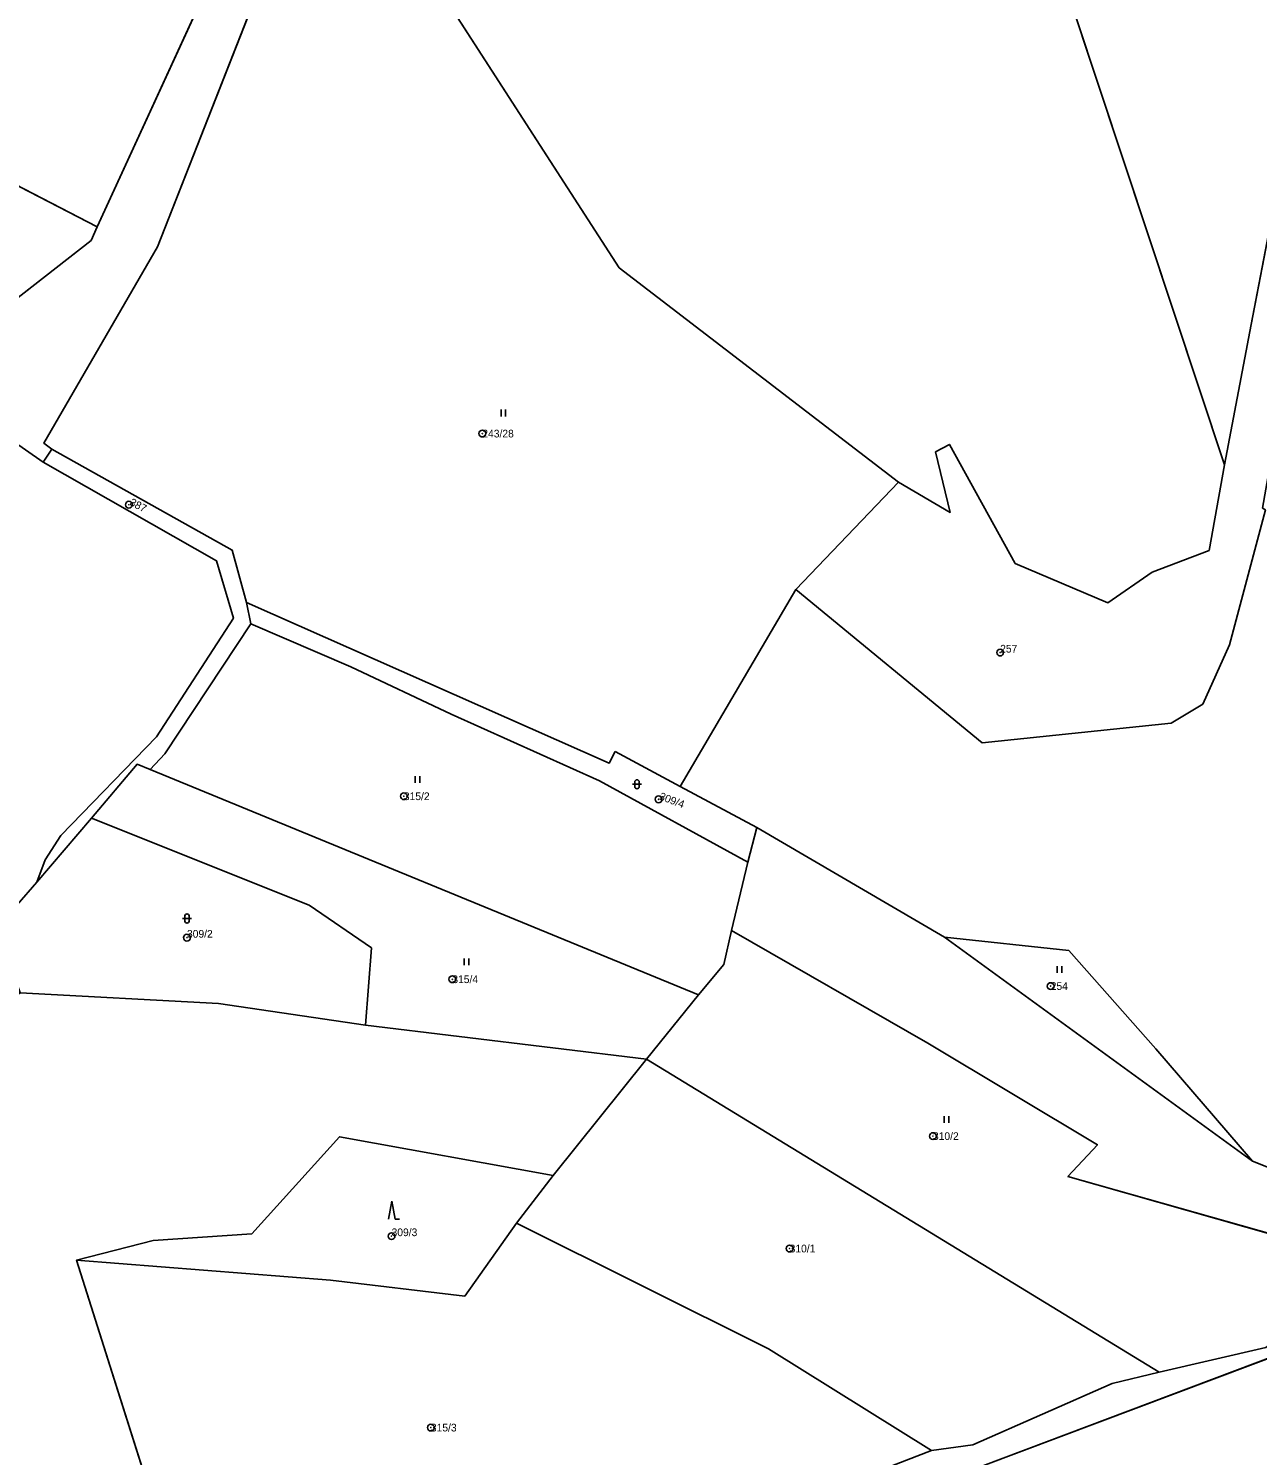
# Model space of a CAD drawing. Extents: x -652854 to -650068, y -1097661 to -1095417.
# Drawn here: x -651121.4 to -650849.8, y -1097086.2 to -1096771 of the extents above; entities that cross this region are included whole.
import ezdxf

# ---------------------------------------------------------------- set-up
doc = ezdxf.new("R2010")
doc.units = 0
for name, color, linetype in [('Definiční body parcel', 7, 'Continuous'), ('Hranice parcel', 7, 'Continuous'), ('Obvody jako plochy', 7, 'Continuous'), ('Parcelní čísla', 7, 'Continuous'), ('Značky kultur', 7, 'Continuous')]:
    doc.layers.add(name, color=color, linetype=linetype)

msp = doc.modelspace()

# ---------------------------------------------------------------- linework, layer by layer
at = {"layer": 'Definiční body parcel'}
for centre, radius in [((-651021.11, -1096860.46), 0.75), ((-651021.11, -1096860.46), 0.0327), ((-651099.22, -1096876.17), 0.75), ((-651099.22, -1096876.17), 0.0327), ((-650906.68, -1096908.84), 0.75), ((-650906.68, -1096908.84), 0.0327), ((-651038.45, -1096940.59), 0.75), ((-651038.45, -1096940.59), 0.0327), ((-650982.16, -1096941.26), 0.75), ((-650982.16, -1096941.26), 0.0327), ((-651086.38, -1096971.83), 0.75), ((-651086.38, -1096971.83), 0.0327), ((-651027.74, -1096981.02), 0.75), ((-651027.74, -1096981.02), 0.0327), ((-650895.51, -1096982.53), 0.75), ((-650895.51, -1096982.53), 0.0327), ((-650921.53, -1097015.68), 0.75), ((-650921.53, -1097015.68), 0.0327), ((-651041.17, -1097037.78), 0.75), ((-651041.17, -1097037.78), 0.0327), ((-650953.2, -1097040.52), 0.75), ((-650953.2, -1097040.52), 0.0327), ((-651032.48, -1097080.08), 0.75), ((-651032.48, -1097080.08), 0.0327)]:
    msp.add_circle(centre, radius, dxfattribs=at)
at = {"layer": 'Hranice parcel'}
for p, q in [((-651054.18, -1096725.78), (-650990.9, -1096823.82)), ((-651106.25, -1096814.79), (-651073.19, -1096742.86)), ((-651064.16, -1096746.02), (-651092.91, -1096819.19)), ((-651234.33, -1096748.53), (-651106.25, -1096814.79)), ((-650857.12, -1096867.39), (-650895.72, -1096750.97)), ((-650839.76, -1096776.84), (-650851.23, -1096836.35)), ((-651107.57, -1096817.82), (-651106.25, -1096814.79)), ((-651148.03, -1096849.31), (-651107.57, -1096817.82)), ((-651092.91, -1096819.19), (-651118.03, -1096862.54)), ((-650990.9, -1096823.82), (-650929.11, -1096871.18)), ((-650851.23, -1096836.35), (-650857.12, -1096867.39)), ((-651118.15, -1096866.81), (-651139.25, -1096852.14)), ((-651118.03, -1096862.54), (-651116.22, -1096863.89)), ((-650917.88, -1096862.87), (-650920.95, -1096864.52)), ((-650903.36, -1096889.13), (-650917.88, -1096862.87)), ((-651118.15, -1096866.81), (-651116.22, -1096863.89)), ((-651116.22, -1096863.89), (-651076.39, -1096886.18)), ((-650920.95, -1096864.52), (-650917.75, -1096877.86)), ((-651079.85, -1096888.57), (-651118.15, -1096866.81)), ((-650857.12, -1096867.39), (-650860.53, -1096886.28)), ((-650929.11, -1096871.18), (-650951.86, -1096894.94)), ((-650917.75, -1096877.86), (-650929.11, -1096871.18)), ((-650855.98, -1096907.12), (-650848.06, -1096877.3)), ((-651076.39, -1096886.18), (-651073.22, -1096897.77)), ((-650860.53, -1096886.28), (-650873.06, -1096891.08)), ((-651076.13, -1096901.24), (-651079.85, -1096888.57)), ((-650882.88, -1096897.84), (-650903.36, -1096889.13)), ((-650873.06, -1096891.08), (-650882.88, -1096897.84)), ((-650993.08, -1096933.27), (-651073.22, -1096897.77)), ((-651073.22, -1096897.77), (-651072.28, -1096902.46)), ((-650951.86, -1096894.94), (-650977.36, -1096938.43)), ((-650951.86, -1096894.94), (-650910.63, -1096928.8)), ((-651093.14, -1096927.43), (-651076.13, -1096901.24)), ((-651072.28, -1096902.46), (-651091.25, -1096931.23)), ((-651072.28, -1096902.46), (-651050.19, -1096912)), ((-650861.91, -1096920.25), (-650855.98, -1096907.12)), ((-651050.19, -1096912), (-651027.98, -1096922.47)), ((-651027.98, -1096922.47), (-650995.25, -1096937.21)), ((-650868.88, -1096924.45), (-650861.91, -1096920.25)), ((-650910.63, -1096928.8), (-650868.88, -1096924.45)), ((-651114.25, -1096949.24), (-651093.14, -1096927.43)), ((-651091.25, -1096931.23), (-651094.49, -1096934.71)), ((-650991.73, -1096930.73), (-650993.08, -1096933.27)), ((-650977.36, -1096938.43), (-650991.73, -1096930.73)), ((-651097.4, -1096933.5), (-651107.5, -1096945.41)), ((-651094.49, -1096934.71), (-651097.4, -1096933.5)), ((-650973.32, -1096984.48), (-651094.49, -1096934.71)), ((-650995.25, -1096937.21), (-650962.41, -1096955.12)), ((-650960.43, -1096947.51), (-650977.36, -1096938.43)), ((-651107.5, -1096945.41), (-651119.55, -1096959.6)), ((-651059.41, -1096964.67), (-651107.5, -1096945.41)), ((-650962.41, -1096955.12), (-650960.43, -1096947.51)), ((-650918.97, -1096971.74), (-650960.43, -1096947.51)), ((-651117.7, -1096954.62), (-651114.25, -1096949.24)), ((-651119.55, -1096959.6), (-651117.7, -1096954.62)), ((-650962.41, -1096955.12), (-650966.07, -1096970.24)), ((-651119.55, -1096959.6), (-651128.3, -1096969.57)), ((-651045.61, -1096974.1), (-651059.41, -1096964.67)), ((-650967.75, -1096977.76), (-650966.07, -1096970.24)), ((-650966.07, -1096970.24), (-650922.68, -1096995.13)), ((-650850.91, -1097021.2), (-650918.97, -1096971.74)), ((-650918.97, -1096971.74), (-650891.5, -1096974.68)), ((-651046.91, -1096991.17), (-651045.61, -1096974.1)), ((-650891.5, -1096974.68), (-650872.31, -1096996.42)), ((-650973.32, -1096984.48), (-650967.75, -1096977.76)), ((-651123.24, -1096984.03), (-651079.38, -1096986.4)), ((-650984.81, -1096998.67), (-650973.32, -1096984.48)), ((-651079.38, -1096986.4), (-651046.91, -1096991.17)), ((-650984.81, -1096998.67), (-651046.91, -1096991.17)), ((-650922.68, -1096995.13), (-650885.18, -1097017.6)), ((-651005.44, -1097024.35), (-650984.81, -1096998.67)), ((-650871.56, -1097067.8), (-650984.81, -1096998.67)), ((-650872.31, -1096996.42), (-650850.91, -1097021.2)), ((-651052.68, -1097015.8), (-651072.08, -1097037.24)), ((-651005.44, -1097024.35), (-651052.68, -1097015.8)), ((-650885.18, -1097017.6), (-650891.69, -1097024.58)), ((-650822.53, -1097032.54), (-650850.91, -1097021.2)), ((-651013.59, -1097034.94), (-651005.44, -1097024.35)), ((-650891.69, -1097024.58), (-650838.85, -1097039.59)), ((-651025, -1097051.04), (-651013.59, -1097034.94)), ((-650957.85, -1097062.7), (-651013.59, -1097034.94)), ((-651093.83, -1097038.77), (-651110.78, -1097043.06)), ((-651072.08, -1097037.24), (-651093.83, -1097038.77)), ((-651110.78, -1097043.06), (-651054.64, -1097047.48)), ((-651092.42, -1097101.02), (-651110.78, -1097043.06)), ((-651054.64, -1097047.48), (-651025, -1097051.04)), ((-650804.25, -1097048.49), (-650910.53, -1097088.56)), ((-650921.88, -1097085.12), (-650957.85, -1097062.7)), ((-650848, -1097062.38), (-650871.56, -1097067.8)), ((-650871.56, -1097067.8), (-650881.93, -1097070.34)), ((-650881.93, -1097070.34), (-650912.69, -1097083.87)), ((-650921.88, -1097085.12), (-650999.97, -1097115.32)), ((-650912.69, -1097083.87), (-650921.88, -1097085.12))]:
    msp.add_line(p, q, dxfattribs=at)
at = {"layer": 'Obvody jako plochy'}
for points in [[(-650799.85, -1096650.9), (-650801.47, -1096660.7), (-650795.97, -1096647.36), (-650807.31, -1096617.17), (-650798.99, -1096582.65), (-650793.31, -1096549.53), (-650785.54, -1096499.95), (-650773.41, -1096422.59), (-650773.25, -1096394.71), (-650771.95, -1096365.02), (-650824.93, -1096315.79), (-650882.2, -1096467.08), (-650940.33, -1096616.41), (-650895.72, -1096750.97), (-650857.12, -1096867.39), (-650851.23, -1096836.35), (-650839.76, -1096776.84), (-650837.51, -1096768.15), (-650819.95, -1096709.68), (-650802.47, -1096650.3)], [(-651377.52, -1096988.66), (-651378.36, -1096871.23), (-651378.55, -1096753.88), (-651366.75, -1096677.34), (-651362.98, -1096681.82), (-651234.33, -1096748.53), (-651106.25, -1096814.79), (-651073.19, -1096742.86), (-651157.36, -1096649.81), (-651239.61, -1096559.6), (-651253.59, -1096559.84), (-651310.77, -1096613.31), (-651432.26, -1096709), (-651516.85, -1096778.46), (-651480.45, -1096885.67), (-651444.66, -1096993.23)], [(-651294.29, -1097048.39), (-651260.99, -1097064.52), (-651242.12, -1096996.77), (-651244.09, -1096981.31), (-651252.18, -1096966.63), (-651247.74, -1096949.65), (-651229.34, -1096915.13), (-651219.12, -1096888.73), (-651191.03, -1096866.63), (-651148.03, -1096849.31), (-651107.57, -1096817.82), (-651106.25, -1096814.79), (-651234.33, -1096748.53), (-651362.98, -1096681.82), (-651366.75, -1096677.34), (-651378.55, -1096753.88), (-651378.36, -1096871.23), (-651377.52, -1096988.66), (-651345.79, -1097007.69), (-651288.56, -1097037.08)], [(-650991.73, -1096930.73), (-650977.36, -1096938.43), (-650951.86, -1096894.94), (-650929.11, -1096871.18), (-650990.9, -1096823.82), (-651054.18, -1096725.78), (-651057.86, -1096732.59), (-651064.16, -1096746.02), (-651092.91, -1096819.19), (-651118.03, -1096862.54), (-651116.22, -1096863.89), (-651076.39, -1096886.18), (-651073.22, -1096897.77), (-650993.08, -1096933.27)], [(-650762.49, -1096937.57), (-650762.99, -1096887.62), (-650838.97, -1096843.48), (-650842.5, -1096841.66), (-650848.73, -1096876.93), (-650848.06, -1096877.3), (-650855.98, -1096907.12), (-650861.91, -1096920.25), (-650868.88, -1096924.45), (-650910.63, -1096928.8), (-650951.86, -1096894.94), (-650977.36, -1096938.43), (-650960.43, -1096947.51), (-650918.97, -1096971.74), (-650891.5, -1096974.68), (-650872.31, -1096996.42), (-650850.91, -1097021.2), (-650822.53, -1097032.54), (-650800.2, -1097006.86), (-650782.46, -1096986.45)], [(-651135.7, -1096978.13), (-651128.3, -1096969.57), (-651119.55, -1096959.6), (-651117.7, -1096954.62), (-651114.25, -1096949.24), (-651093.14, -1096927.43), (-651076.13, -1096901.24), (-651079.85, -1096888.57), (-651118.15, -1096866.81), (-651139.25, -1096852.14), (-651185.65, -1096873.07), (-651212.01, -1096895.47), (-651221.71, -1096910.45), (-651238.32, -1096950.99), (-651239.04, -1096997.1), (-651245.41, -1097021.38), (-651241.47, -1097030.24)], [(-651116.22, -1096863.89), (-651118.15, -1096866.81), (-651079.85, -1096888.57), (-651076.13, -1096901.24), (-651093.14, -1096927.43), (-651114.25, -1096949.24), (-651117.7, -1096954.62), (-651119.55, -1096959.6), (-651107.5, -1096945.41), (-651097.4, -1096933.5), (-651094.49, -1096934.71), (-651091.25, -1096931.23), (-651072.28, -1096902.46), (-651073.22, -1096897.77), (-651076.39, -1096886.18)], [(-650991.73, -1096930.73), (-650993.08, -1096933.27), (-651073.22, -1096897.77), (-651072.28, -1096902.46), (-651050.19, -1096912), (-651027.98, -1096922.47), (-650995.25, -1096937.21), (-650962.41, -1096955.12), (-650960.43, -1096947.51), (-650977.36, -1096938.43)], [(-651072.28, -1096902.46), (-651091.25, -1096931.23), (-651094.49, -1096934.71), (-650973.32, -1096984.48), (-650967.75, -1096977.76), (-650966.07, -1096970.24), (-650962.41, -1096955.12), (-650995.25, -1096937.21), (-651027.98, -1096922.47), (-651050.19, -1096912)], [(-651097.4, -1096933.5), (-651107.5, -1096945.41), (-651059.41, -1096964.67), (-651045.61, -1096974.1), (-651046.91, -1096991.17), (-650984.81, -1096998.67), (-650973.32, -1096984.48), (-651094.49, -1096934.71)], [(-651107.5, -1096945.41), (-651119.55, -1096959.6), (-651128.3, -1096969.57), (-651123.24, -1096984.03), (-651079.38, -1096986.4), (-651046.91, -1096991.17), (-651045.61, -1096974.1), (-651059.41, -1096964.67)], [(-650922.68, -1096995.13), (-650966.07, -1096970.24), (-650967.75, -1096977.76), (-650973.32, -1096984.48), (-650984.81, -1096998.67), (-650871.56, -1097067.8), (-650848, -1097062.38), (-650834.74, -1097052.93), (-650838.85, -1097039.59), (-650891.69, -1097024.58), (-650885.18, -1097017.6)], [(-650850.91, -1097021.2), (-650872.31, -1096996.42), (-650891.5, -1096974.68), (-650918.97, -1096971.74)], [(-651105.3, -1097152.59), (-651093.01, -1097103.7), (-651092.42, -1097101.02), (-651110.78, -1097043.06), (-651093.83, -1097038.77), (-651072.08, -1097037.24), (-651052.68, -1097015.8), (-651005.44, -1097024.35), (-650984.81, -1096998.67), (-651046.91, -1096991.17), (-651079.38, -1096986.4), (-651123.24, -1096984.03), (-651223.1, -1097052.93), (-651170.2, -1097087.35), (-651161.42, -1097100.33), (-651159.02, -1097111.66), (-651169.04, -1097168.66), (-651165.31, -1097170.68)], [(-650871.56, -1097067.8), (-650984.81, -1096998.67), (-651005.44, -1097024.35), (-651013.59, -1097034.94), (-650957.85, -1097062.7), (-650921.88, -1097085.12), (-650912.69, -1097083.87), (-650881.93, -1097070.34)], [(-651093.83, -1097038.77), (-651110.78, -1097043.06), (-651054.64, -1097047.48), (-651025, -1097051.04), (-651013.59, -1097034.94), (-651005.44, -1097024.35), (-651052.68, -1097015.8), (-651072.08, -1097037.24)], [(-650999.97, -1097115.32), (-650921.88, -1097085.12), (-650957.85, -1097062.7), (-651013.59, -1097034.94), (-651025, -1097051.04), (-651054.64, -1097047.48), (-651110.78, -1097043.06), (-651092.42, -1097101.02), (-651093.01, -1097103.7), (-651065.33, -1097109.35), (-651030.25, -1097117.65)], [(-650773.96, -1097109.54), (-650775.22, -1097043.42), (-650804.25, -1097048.49), (-650910.53, -1097088.56), (-651000.14, -1097122.08), (-650984.11, -1097126.35), (-650968.29, -1097125.74), (-650958.37, -1097127.66), (-650929.12, -1097122.49), (-650909.36, -1097114.39), (-650889.89, -1097141.73), (-650828.93, -1097134.46), (-650799.57, -1097135.85), (-650754.48, -1097130.94)]]:
    msp.add_lwpolyline(points, close=True, dxfattribs=at)
for points in [[(-650997.98, -1096467.04), (-651000.71, -1096567.63), (-651003.94, -1096568.48), (-651004.79, -1096566.57), (-651020.73, -1096600.77), (-651039.71, -1096659.27), (-651051.76, -1096702.47), (-651070.68, -1096737.5), (-651073.19, -1096742.86), (-651106.25, -1096814.79), (-651107.57, -1096817.82), (-651148.03, -1096849.31), (-651191.03, -1096866.63), (-651219.12, -1096888.73), (-651229.34, -1096915.13), (-651247.74, -1096949.65), (-651252.18, -1096966.63), (-651244.09, -1096981.31), (-651242.12, -1096996.77), (-651260.99, -1097064.52), (-651285.08, -1097185.42)], [(-650986.75, -1096469.56), (-650996.98, -1096566.77), (-651005.54, -1096598.62), (-651013.64, -1096606.83), (-651031.97, -1096667.36), (-651044.25, -1096705.46), (-651054.18, -1096725.78), (-650990.9, -1096823.82), (-650929.11, -1096871.18), (-650917.75, -1096877.86), (-650920.95, -1096864.52), (-650917.88, -1096862.87), (-650903.36, -1096889.13), (-650882.88, -1096897.84), (-650873.06, -1096891.08), (-650860.53, -1096886.28), (-650857.12, -1096867.39), (-650895.72, -1096750.97), (-650940.33, -1096616.41), (-650882.2, -1096467.08)], [(-651265.36, -1097103.05), (-651257.34, -1097063.72), (-651247.51, -1097028.99), (-651245.41, -1097021.38), (-651239.04, -1096997.1), (-651238.32, -1096950.99), (-651221.71, -1096910.45), (-651212.01, -1096895.47), (-651185.65, -1096873.07), (-651139.25, -1096852.14), (-651118.15, -1096866.81), (-651116.22, -1096863.89), (-651118.03, -1096862.54), (-651092.91, -1096819.19), (-651064.16, -1096746.02), (-651057.86, -1096732.59), (-651054.18, -1096725.78), (-651044.25, -1096705.46), (-651031.97, -1096667.36), (-651013.64, -1096606.83), (-651005.54, -1096598.62), (-650996.98, -1096566.77), (-650986.75, -1096469.56)], [(-650839.76, -1096776.84), (-650851.23, -1096836.35), (-650857.12, -1096867.39), (-650860.53, -1096886.28), (-650873.06, -1096891.08), (-650882.88, -1096897.84), (-650903.36, -1096889.13), (-650917.88, -1096862.87), (-650920.95, -1096864.52), (-650917.75, -1096877.86), (-650929.11, -1096871.18), (-650951.86, -1096894.94), (-650910.63, -1096928.8), (-650868.88, -1096924.45), (-650861.91, -1096920.25), (-650855.98, -1096907.12), (-650848.06, -1096877.3)], [(-650822.53, -1097032.54), (-650850.91, -1097021.2), (-650918.97, -1096971.74), (-650960.43, -1096947.51), (-650962.41, -1096955.12), (-650966.07, -1096970.24), (-650922.68, -1096995.13), (-650885.18, -1097017.6), (-650891.69, -1097024.58), (-650838.85, -1097039.59)], [(-650910.53, -1097088.56), (-650804.25, -1097048.49)], [(-650848, -1097062.38), (-650871.56, -1097067.8), (-650881.93, -1097070.34), (-650912.69, -1097083.87), (-650921.88, -1097085.12), (-650999.97, -1097115.32)]]:
    msp.add_lwpolyline(points, dxfattribs=at)
at = {"layer": 'Značky kultur'}
for p, q in [((-651016.987, -1096855.165), (-651016.987, -1096856.665)), ((-651015.965, -1096856.665), (-651015.965, -1096855.165)), ((-651035.957, -1096936.155), (-651035.957, -1096937.655)), ((-651034.935, -1096937.655), (-651034.935, -1096936.155)), ((-650987.92, -1096937.95), (-650985.92, -1096937.95)), ((-650987.42, -1096938.45), (-650987.42, -1096937.45)), ((-650986.42, -1096938.45), (-650986.42, -1096937.45)), ((-651086.88, -1096968.1), (-651086.88, -1096967.1)), ((-651085.88, -1096968.1), (-651085.88, -1096967.1)), ((-651087.38, -1096967.6), (-651085.38, -1096967.6)), ((-651025.127, -1096976.435), (-651025.127, -1096977.935)), ((-651024.105, -1096977.935), (-651024.105, -1096976.435)), ((-650894.097, -1096978.095), (-650894.097, -1096979.595)), ((-650893.075, -1096979.595), (-650893.075, -1096978.095)), ((-650919.057, -1097011.245), (-650919.057, -1097012.745)), ((-650918.035, -1097012.745), (-650918.035, -1097011.245)), ((-651041.132, -1097030.019), (-651041.865, -1097034.019)), ((-651041.132, -1097030.019), (-651040.399, -1097034.019)), ((-651040.399, -1097034.019), (-651039.399, -1097034.019))]:
    msp.add_line(p, q, dxfattribs=at)
for centre, start, end in [((-650986.92, -1096937.45), 0, 180), ((-650986.92, -1096938.45), 180, 0), ((-651086.38, -1096967.1), 0, 180), ((-651086.38, -1096968.1), 180, 0)]:
    msp.add_arc(centre, 0.5, start, end, dxfattribs=at)

# ---------------------------------------------------------------- texts
at = {"layer": 'Parcelní čísla'}
for s, p in [('243/28', (-651021.11, -1096861.31)), ('257', (-650906.68, -1096908.84)), ('315/2', (-651038.45, -1096941.44)), ('309/2', (-651086.38, -1096971.83)), ('315/4', (-651027.74, -1096981.87)), ('254', (-650895.51, -1096983.38)), ('310/2', (-650921.53, -1097016.53)), ('309/3', (-651041.17, -1097037.78)), ('310/1', (-650953.2, -1097041.37)), ('315/3', (-651032.48, -1097080.93))]:
    msp.add_text(s, height=1.7, dxfattribs=at).set_placement(p)
for s, rotation, p in [('387', 332.28, (-651099.22, -1096876.17)), ('309/4', 339.462, (-650982.16, -1096941.26))]:
    msp.add_text(s, height=1.7, rotation=rotation, dxfattribs=at).set_placement(p)

doc.saveas('drawing.dxf')
